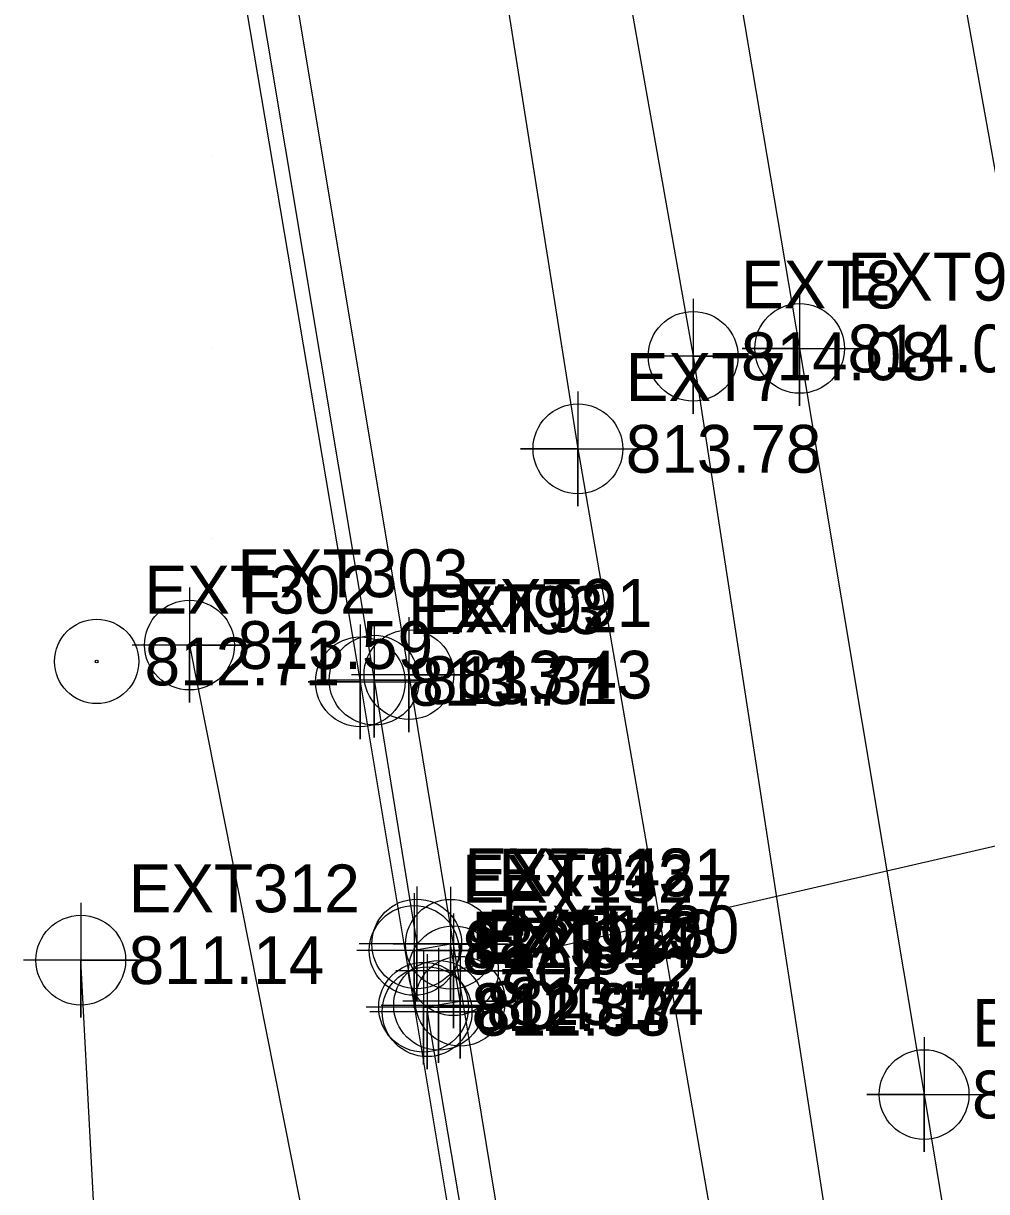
# Model space of a CAD drawing. Extents: x 1762120 to 1766775, y 709485 to 712965.
# Drawn here: x 1763760.2 to 1763810.5, y 712815.9 to 712876.9 of the extents above; entities that cross this region are included whole.
import ezdxf

# ---------------------------------------------------------------- set-up
doc = ezdxf.new("R2010")
doc.units = 0
for name, color, linetype in [('Exist DTM Breakline', 7, 'Continuous'), ('Exist DTM Breakline Cogo Elevation', 7, 'Continuous'), ('Exist DTM Breakline Cogo Number', 7, 'Continuous'), ('Exist DTM Breakline Cogo Point CELL', 7, 'Continuous'), ('Exist DTM Crownline', 7, 'Continuous'), ('Exist DTM Crownline Cogo Elevation', 7, 'Continuous'), ('Exist DTM Crownline Cogo Number', 7, 'Continuous'), ('Exist DTM Crownline Cogo Point CELL', 7, 'Continuous'), ('Exist DTM Drainline', 7, 'Continuous'), ('Exist DTM Drainline Cogo Elevation', 7, 'Continuous'), ('Exist DTM Drainline Cogo Number', 7, 'Continuous'), ('Exist DTM Drainline Cogo Point CELL', 7, 'Continuous'), ('Exist DTM QL2 LIDAR Elevation Point', 7, 'Continuous'), ('Exist Property Iron Pin CELL', 7, 'Continuous'), ('Exist Property Iron Pin Cogo Elevation', 7, 'Continuous'), ('Exist Property Iron Pin Cogo Number', 7, 'Continuous'), ('Exist Roads Curbs', 7, 'Continuous'), ('Exist Roads Curbs Cogo Elevation', 7, 'Continuous'), ('Exist Roads Curbs Cogo Number', 7, 'Continuous'), ('Exist Roads Curbs Cogo Point CELL', 7, 'Continuous'), ('Exist Roads EOP', 7, 'Continuous'), ('Exist Roads EOP Cogo Elevation', 7, 'Continuous'), ('Exist Roads EOP Cogo Number', 7, 'Continuous'), ('Exist Roads EOP Cogo Point CELL', 7, 'Continuous'), ('Exist Roads EOT', 7, 'Continuous'), ('Exist Roads EOT Cogo Elevation', 7, 'Continuous'), ('Exist Roads EOT Cogo Number', 7, 'Continuous'), ('Exist Roads EOT Cogo Point CELL', 7, 'Continuous'), ('Exist Structure Minor Drop Inlet', 7, 'Continuous'), ('Exist Structure Minor Drop Inlet Cogo Elevation', 7, 'Continuous'), ('Exist Structure Minor Drop Inlet Cogo Number', 7, 'Continuous'), ('Exist Structure Minor Drop Inlet Cogo Point CELL', 7, 'Continuous'), ('Exist Structure Minor Pipes RCP 15 Inch', 7, 'Continuous'), ('Exist Structure Minor Pipes RCP 15 Inch Cogo Elevation', 7, 'Continuous'), ('Exist Structure Minor Pipes RCP 15 Inch Cogo Number', 7, 'Continuous'), ('Exist Structure Minor Pipes RCP 15 Inch Cogo Point CELL', 7, 'Continuous')]:
    doc.layers.add(name, color=color, linetype=linetype)

msp = doc.modelspace()

# ---------------------------------------------------------------- linework, layer by layer
at = {"layer": 'Exist DTM Breakline'}
msp.add_lwpolyline([(1763768.874, 712844.443), (1763776.006, 712808.452), (1763782.443, 712776.817), (1763789.545, 712738.641), (1763792.599, 712718.345), (1763784.294, 712719.006), (1763777.898, 712733.601), (1763771.211, 712768.686), (1763764.647, 712800.553), (1763763.195, 712827.976)], dxfattribs=at)
at = {"layer": 'Exist DTM Breakline Cogo Point CELL'}
for points in [[(1763768.874, 712847.443), (1763768.874, 712841.443), (1763768.874, 712844.443), (1763771.874, 712844.443), (1763765.874, 712844.443)], [(1763763.195, 712830.976), (1763763.195, 712824.976), (1763763.195, 712827.976), (1763766.195, 712827.976), (1763760.195, 712827.976)]]:
    msp.add_lwpolyline(points, dxfattribs=at)
for centre in [(1763768.874, 712844.443), (1763763.195, 712827.976)]:
    msp.add_circle(centre, 2.344, dxfattribs=at)
at = {"layer": 'Exist DTM Crownline'}
msp.add_lwpolyline([(1763783.92, 712926.058), (1763790.262, 712887.319), (1763795.183, 712859.532), (1763803.032, 712808.629), (1763808.926, 712776.275), (1763814.523, 712743.371), (1763820.27, 712708.85), (1763825.749, 712675.916), (1763832.222, 712637.522), (1763836.733, 712610.54), (1763843.626, 712568.925)], dxfattribs=at)
at = {"layer": 'Exist DTM Crownline Cogo Point CELL'}
msp.add_lwpolyline([(1763795.183, 712862.532), (1763795.183, 712856.532), (1763795.183, 712859.532), (1763798.183, 712859.532), (1763792.183, 712859.532)], dxfattribs=at)
msp.add_circle((1763795.183, 712859.532), 2.344, dxfattribs=at)
at = {"layer": 'Exist DTM Drainline'}
for points in [[(1763765.212, 712922.089), (1763772.003, 712881.594), (1763778.522, 712842.61), (1763780.745, 712828.822)], [(1763781.288, 712825.282), (1763786.304, 712795.661), (1763793.687, 712751.498), (1763799.331, 712717.754), (1763805.438, 712681.563), (1763811.952, 712643.035), (1763816.532, 712615.56)]]:
    msp.add_lwpolyline(points, dxfattribs=at)
at = {"layer": 'Exist DTM Drainline Cogo Point CELL'}
for points in [[(1763778.522, 712845.61), (1763778.522, 712839.61), (1763778.522, 712842.61), (1763781.522, 712842.61), (1763775.522, 712842.61)], [(1763780.745, 712831.822), (1763780.745, 712825.822), (1763780.745, 712828.822), (1763783.745, 712828.822), (1763777.745, 712828.822)], [(1763781.288, 712828.282), (1763781.288, 712822.282), (1763781.288, 712825.282), (1763784.288, 712825.282), (1763778.288, 712825.282)]]:
    msp.add_lwpolyline(points, dxfattribs=at)
for centre in [(1763778.522, 712842.61), (1763780.745, 712828.822), (1763781.288, 712825.282)]:
    msp.add_circle(centre, 2.344, dxfattribs=at)
at = {"layer": 'Exist DTM QL2 LIDAR Elevation Point'}
for p, q in [((1763770, 712870), (1763770, 712870)), ((1763770, 712860), (1763770, 712860)), ((1763770, 712850), (1763770, 712850))]:
    msp.add_line(p, q, dxfattribs=at)
at = {"layer": 'Exist Property Iron Pin CELL'}
for radius in [2.203, 0.0707]:
    msp.add_circle((1763764.025, 712843.586), radius, dxfattribs=at)
at = {"layer": 'Exist Roads Curbs'}
msp.add_lwpolyline([(1763764.468, 712921.993), (1763771.224, 712881.371), (1763777.799, 712842.52), (1763785.017, 712799.156), (1763793.002, 712751.297), (1763798.517, 712717.85), (1763798.751, 712716.41), (1763801.856, 712697.916), (1763802.154, 712696.936), (1763804.688, 712681.498), (1763811.149, 712642.967), (1763816.501, 712611.824), (1763823.372, 712570.121)], dxfattribs=at)
at = {"layer": 'Exist Roads Curbs Cogo Point CELL'}
msp.add_lwpolyline([(1763777.799, 712845.52), (1763777.799, 712839.52), (1763777.799, 712842.52), (1763775.069, 712842.52), (1763780.799, 712842.52)], dxfattribs=at)
msp.add_circle((1763777.799, 712842.52), 2.344, dxfattribs=at)
at = {"layer": 'Exist Roads EOP'}
msp.add_lwpolyline([(1763767.083, 712922.223), (1763773.823, 712881.974), (1763780.335, 712842.895), (1763788.848, 712791.154), (1763795.539, 712751.806), (1763801.2, 712718.139), (1763807.385, 712682.013), (1763813.812, 712643.387), (1763818.936, 712612.35), (1763825.965, 712570.729)], dxfattribs=at)
at = {"layer": 'Exist Roads EOP Cogo Point CELL'}
msp.add_lwpolyline([(1763780.335, 712845.895), (1763780.335, 712839.895), (1763780.335, 712842.895), (1763783.335, 712842.895), (1763777.335, 712842.895)], dxfattribs=at)
msp.add_circle((1763780.335, 712842.895), 2.344, dxfattribs=at)
at = {"layer": 'Exist Roads EOT'}
msp.add_line((1763815.792, 712842.322), (1763808.078, 712885.317), dxfattribs=at)
for points in [[(1763789.832, 712926.884), (1763795.992, 712888.052), (1763800.75, 712859.942), (1763807.254, 712820.955), (1763816.86, 712762.721), (1763822.148, 712731.849), (1763825.695, 712709.767), (1763831.213, 712676.817), (1763837.744, 712638.56), (1763842.2, 712611.183), (1763849.139, 712569.759)], [(1763777.488, 712924.55), (1763781.487, 712903.204), (1763789.164, 712854.697), (1763797.205, 712808.308), (1763802.541, 712775.258), (1763808.303, 712742.168), (1763814.095, 712707.894), (1763819.559, 712674.99), (1763826.1, 712636.377), (1763830.485, 712609.669), (1763837.441, 712567.81)]]:
    msp.add_lwpolyline(points, dxfattribs=at)
at = {"layer": 'Exist Roads EOT Cogo Point CELL'}
for points in [[(1763800.75, 712862.942), (1763800.75, 712856.942), (1763800.75, 712859.942), (1763797.75, 712859.942), (1763803.75, 712859.942)], [(1763789.164, 712857.697), (1763789.164, 712851.697), (1763789.164, 712854.697), (1763786.164, 712854.697), (1763792.164, 712854.697)], [(1763807.254, 712823.955), (1763807.254, 712817.955), (1763807.254, 712820.955), (1763804.254, 712820.955), (1763810.254, 712820.955)]]:
    msp.add_lwpolyline(points, dxfattribs=at)
for centre in [(1763800.75, 712859.942), (1763789.164, 712854.697), (1763807.254, 712820.955)]:
    msp.add_circle(centre, 2.344, dxfattribs=at)
at = {"layer": 'Exist Structure Minor Drop Inlet'}
msp.add_lwpolyline([(1763781.105, 712825.518), (1763783.019, 712825.833), (1763782.51, 712828.81), (1763780.61, 712828.485)], dxfattribs=at)
at = {"layer": 'Exist Structure Minor Drop Inlet Cogo Point CELL'}
for points in [[(1763780.61, 712831.485), (1763780.61, 712825.485), (1763780.61, 712828.485), (1763783.61, 712828.485), (1763777.61, 712828.485)], [(1763782.51, 712831.81), (1763782.51, 712825.81), (1763782.51, 712828.81), (1763785.51, 712828.81), (1763779.51, 712828.81)], [(1763781.105, 712828.518), (1763781.105, 712822.518), (1763781.105, 712825.518), (1763784.105, 712825.518), (1763778.105, 712825.518)], [(1763783.019, 712828.833), (1763783.019, 712822.833), (1763783.019, 712825.833), (1763786.019, 712825.833), (1763780.019, 712825.833)]]:
    msp.add_lwpolyline(points, dxfattribs=at)
for centre in [(1763780.61, 712828.485), (1763782.51, 712828.81), (1763781.105, 712825.518), (1763783.019, 712825.833)]:
    msp.add_circle(centre, 2.344, dxfattribs=at)
at = {"layer": 'Exist Structure Minor Pipes RCP 15 Inch'}
msp.add_line((1763816.852, 712835.285), (1763782.661, 712827.424), dxfattribs=at)
at = {"layer": 'Exist Structure Minor Pipes RCP 15 Inch Cogo Point CELL'}
for points in [[(1763782.661, 712830.424), (1763782.661, 712824.424), (1763782.661, 712827.424), (1763785.661, 712827.424), (1763779.661, 712827.424)], [(1763781.886, 712828.616), (1763781.886, 712822.616), (1763781.886, 712825.616), (1763784.886, 712825.616), (1763778.886, 712825.616)]]:
    msp.add_lwpolyline(points, dxfattribs=at)
for centre in [(1763782.661, 712827.424), (1763781.886, 712825.616)]:
    msp.add_circle(centre, 2.344, dxfattribs=at)

# ---------------------------------------------------------------- texts
at = {"layer": 'Exist DTM Breakline Cogo Elevation'}
for s, p in [('813.59', (1763771.374, 712843.193)), ('811.14', (1763765.695, 712826.726))]:
    msp.add_text(s, height=2.5, dxfattribs=at).set_placement(p)
at = {"layer": 'Exist DTM Breakline Cogo Number'}
for s, p in [('EXT303', (1763771.374, 712846.943)), ('EXT312', (1763765.695, 712830.476))]:
    msp.add_text(s, height=2.5, dxfattribs=at).set_placement(p)
at = {"layer": 'Exist DTM Crownline Cogo Elevation'}
msp.add_text('814.08', height=2.5, dxfattribs=at).set_placement((1763797.683, 712858.282))
at = {"layer": 'Exist DTM Crownline Cogo Number'}
msp.add_text('EXT8', height=2.5, dxfattribs=at).set_placement((1763797.683, 712862.032))
at = {"layer": 'Exist DTM Drainline Cogo Elevation'}
for s, p in [('813.31', (1763781.022, 712841.36)), ('812.94', (1763783.245, 712827.572)), ('812.93', (1763783.788, 712824.032))]:
    msp.add_text(s, height=2.5, dxfattribs=at).set_placement(p)
at = {"layer": 'Exist DTM Drainline Cogo Number'}
for s, p in [('EXT92', (1763781.022, 712845.11)), ('EXT94', (1763783.245, 712831.322)), ('EXT95', (1763783.788, 712827.782))]:
    msp.add_text(s, height=2.5, dxfattribs=at).set_placement(p)
at = {"layer": 'Exist Property Iron Pin Cogo Elevation'}
msp.add_text('812.71', height=2.5, dxfattribs=at).set_placement((1763766.525, 712842.336))
at = {"layer": 'Exist Property Iron Pin Cogo Number'}
msp.add_text('EXT302', height=2.5, dxfattribs=at).set_placement((1763766.525, 712846.086))
at = {"layer": 'Exist Roads Curbs Cogo Elevation'}
msp.add_text('813.77', height=2.5, dxfattribs=at).set_placement((1763780.299, 712841.27))
at = {"layer": 'Exist Roads Curbs Cogo Number'}
msp.add_text('EXT93', height=2.5, dxfattribs=at).set_placement((1763780.299, 712845.02))
at = {"layer": 'Exist Roads EOP Cogo Elevation'}
msp.add_text('813.43', height=2.5, dxfattribs=at).set_placement((1763782.835, 712841.645))
at = {"layer": 'Exist Roads EOP Cogo Number'}
msp.add_text('EXT91', height=2.5, dxfattribs=at).set_placement((1763782.835, 712845.395))
at = {"layer": 'Exist Roads EOT Cogo Elevation'}
for s, p in [('814.03', (1763803.25, 712858.692)), ('813.78', (1763791.664, 712853.447)), ('813.36', (1763809.754, 712819.705))]:
    msp.add_text(s, height=2.5, dxfattribs=at).set_placement(p)
at = {"layer": 'Exist Roads EOT Cogo Number'}
for s, p in [('EXT9', (1763803.25, 712862.442)), ('EXT7', (1763791.664, 712857.197)), ('EXT10', (1763809.754, 712823.455))]:
    msp.add_text(s, height=2.5, dxfattribs=at).set_placement(p)
at = {"layer": 'Exist Structure Minor Drop Inlet Cogo Elevation'}
for s, p in [('813.14', (1763785.01, 712827.56)), ('812.85', (1763783.11, 712827.235)), ('813.14', (1763785.519, 712824.583)), ('812.87', (1763783.605, 712824.268))]:
    msp.add_text(s, height=2.5, dxfattribs=at).set_placement(p)
at = {"layer": 'Exist Structure Minor Drop Inlet Cogo Number'}
for s, p in [('EXT131', (1763785.01, 712831.31)), ('EXT132', (1763783.11, 712830.985)), ('EXT130', (1763785.519, 712828.333)), ('EXT129', (1763783.605, 712828.018))]:
    msp.add_text(s, height=2.5, dxfattribs=at).set_placement(p)
at = {"layer": 'Exist Structure Minor Pipes RCP 15 Inch Cogo Elevation'}
for s, p in [('804.12', (1763785.161, 712826.174)), ('804.17', (1763784.386, 712824.366))]:
    msp.add_text(s, height=2.5, dxfattribs=at).set_placement(p)
at = {"layer": 'Exist Structure Minor Pipes RCP 15 Inch Cogo Number'}
for s, p in [('EXT127', (1763785.161, 712829.924)), ('EXT128', (1763784.386, 712828.116))]:
    msp.add_text(s, height=2.5, dxfattribs=at).set_placement(p)

doc.saveas('drawing.dxf')
